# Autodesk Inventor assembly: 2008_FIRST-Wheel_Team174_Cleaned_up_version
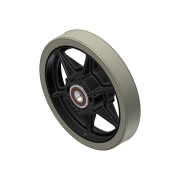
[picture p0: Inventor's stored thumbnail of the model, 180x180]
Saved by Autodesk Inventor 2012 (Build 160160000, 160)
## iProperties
Created: 2011-01
Part Number: 2008_FIRST-Wheel_Team174_Cleaned_up_version
Document SubType Name: Assembly
Designer: Alex
Mass: 283.694 g
Surface Area: 968.22 cm^2
Volume: 216.994 cm^3
Density: 1.30738 g/cm^3
Author: Alex
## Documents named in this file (4)
- C:\Users\Owner\Documents\Robotics\Mechanical Design\Parts\Wheels\2008-FIRST-Wheel\2008_FIRST-Wheel_Team174_Cleaned_up_version.iam
- C:\Users\Owner\Documents\Robotics\Mechanical Design\Parts\Wheels\2008-FIRST-Wheel\Hub for stress.ipt
- C:\Users\Owner\Documents\Robotics\Mechanical Design\Parts\Wheels\2008-FIRST-Wheel\Tread for stress.ipt
- C:\Users\Owner\Documents\Robotics\Mechanical Design\Parts\Bearings and Bushings\Roller Bearings\Roller Bearing, Flanged, 0.500 in ID.ipt
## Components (4 placed, 3 different names)
1. Hub for stress:1 — Insert:1, Insert:2, Insert:3
2. Tread for stress:1 — Insert:1
3. Roller Bearing, Flanged, 0.500 in ID:1 — Insert:2
4. Roller Bearing, Flanged, 0.500 in ID:2 — Insert:3
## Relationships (3: Insert 3)
- Insert:1: Hub for stress:1 ↔ Tread for stress:1
- Insert:2: Hub for stress:1 ↔ Roller Bearing, Flanged, 0.500 in ID:1
- Insert:3: Hub for stress:1 ↔ Roller Bearing, Flanged, 0.500 in ID:2
## Named parameters: sa_0 = 0, sa_1 = 0, sa_2 = -166808.325 mm
